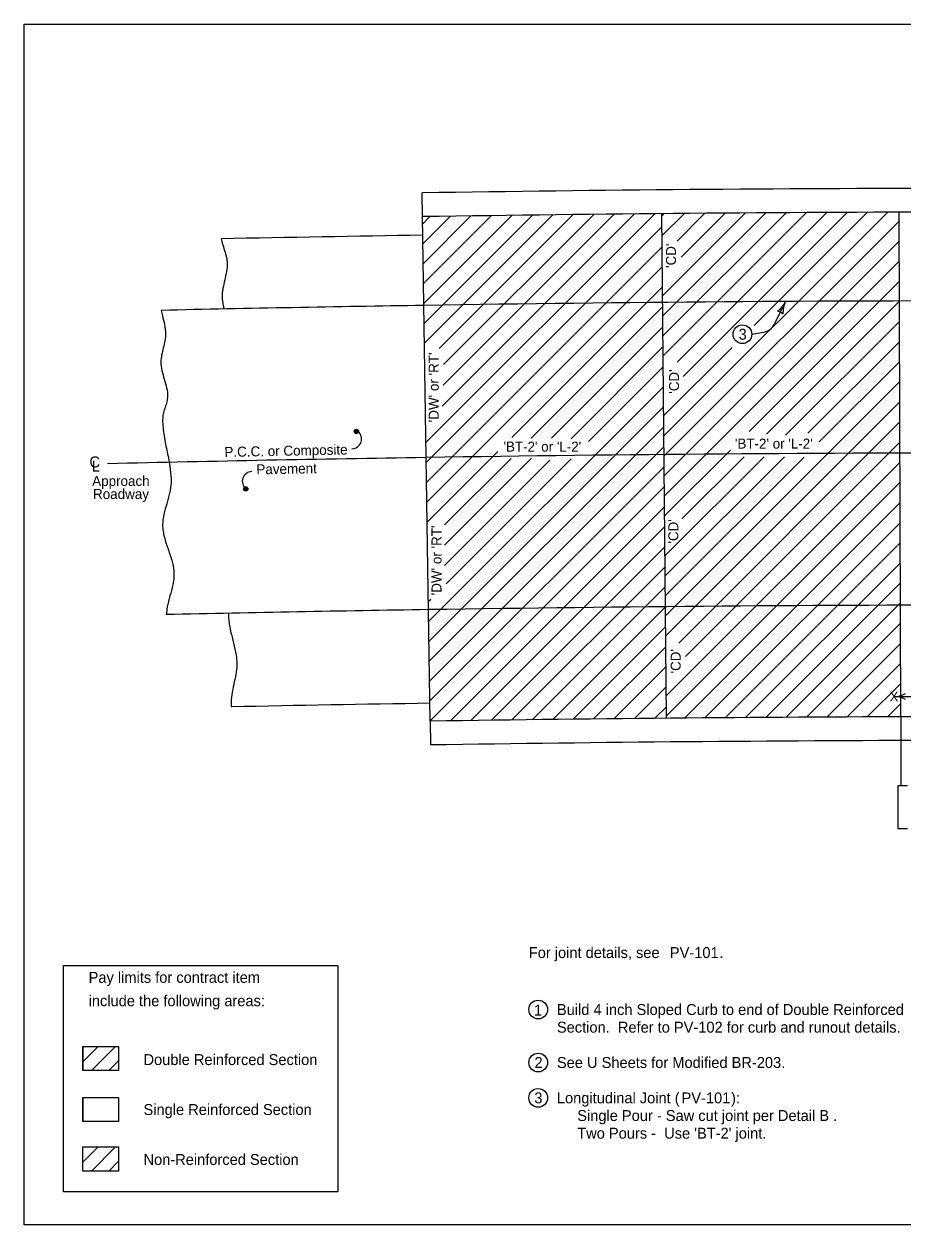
# Model space of a CAD drawing. Extents: x 10130 to 81668, y 5440 to 21644.
# Drawn here: x 20933 to 22410, y 7924 to 9944 of the extents above; entities that cross this region are included whole.
import ezdxf

# ---------------------------------------------------------------- set-up
doc = ezdxf.new("R2010")
doc.units = 0
for name, color, linetype in [('Default', 7, 'Continuous'), ('dsnStdBlockModified', 7, 'Continuous'), ('dsnStdBorder', 7, 'Continuous'), ('dsnstdModifiedBlock', 7, 'Continuous'), ('SheetBorder', 7, 'Continuous')]:
    doc.layers.add(name, color=color, linetype=linetype)

msp = doc.modelspace()

# ---------------------------------------------------------------- linework, layer by layer
at = {"layer": 'Default'}
for p, q in [((21602.2, 9620), (21601.6, 9660)), ((21615.3, 8771.5), (21615.9, 8731.5))]:
    msp.add_line(p, q, dxfattribs=at)
for radius, start in [(65123.7, 89.30428), (64195, 89.350122)]:
    msp.add_arc((22609.7, -55455.9), radius, start, 90.886963, dxfattribs=at)
for points in [[(21264.2, 9582.7), (21265.1, 9578.5), (21268.6, 9566.3), (21272.2, 9554.1), (21273.5, 9548), (21273.9, 9544.9), (21274.1, 9541.8), (21272.9, 9527.7), (21269.9, 9513.6), (21266.9, 9499.5), (21265.8, 9492.4), (21265.6, 9488.9), (21265.6, 9485.4), (21267.4, 9470.4), (21268.7, 9464.7)], [(21163, 9462.4), (21165.2, 9453.1), (21168.8, 9438.2), (21170.5, 9423.2), (21169.4, 9411.3), (21166.6, 9399.5), (21163.9, 9387.7), (21162.5, 9375.9), (21164.3, 9361.2), (21168.3, 9346.6), (21172.2, 9331.9), (21173.8, 9317.3), (21172.5, 9308.4), (21169.8, 9299.5), (21167, 9290.7), (21165.6, 9281.7), (21165.9, 9268.2), (21167.5, 9254.6), (21172.5, 9227.3), (21177.7, 9200), (21179.6, 9179.6), (21179.7, 9172.8), (21177.3, 9155), (21172.5, 9137.2), (21167.7, 9119.4), (21165.5, 9101.6), (21166.3, 9091.2), (21168.4, 9080.8), (21174.9, 9060.3), (21181.5, 9039.8), (21184.6, 9019.2), (21184.1, 9009.9), (21182.5, 9000.7), (21177.9, 8982.1), (21173.3, 8963.5), (21171.6, 8950.6)], [(21276.5, 8952.9), (21276.4, 8947.2), (21276.6, 8942.2), (21277.1, 8937.2), (21278.8, 8927.3), (21283.5, 8907.5), (21288.1, 8887.6), (21289.8, 8877.7), (21290.1, 8872.7), (21290.3, 8867.7), (21289.9, 8859), (21288.6, 8850.4), (21285.1, 8833.2), (21281.8, 8815.9), (21280.9, 8798.6), (21281.1, 8795.5)]]:
    msp.add_spline(points, degree=3, dxfattribs=at)
at = {"layer": 'dsnStdBlockModified'}
for p, q in [((22194.2, 9439.4), (22212.9, 9477.3)), ((22155.9, 9422.2), (22175.4, 9425.5)), ((22394.6, 8812.8), (22425.9, 8812.8)), ((21031.6, 8224.3), (21091.3, 8224.3)), ((21031.6, 8183.8), (21031.6, 8224.3)), ((21091.3, 8224.3), (21091.3, 8183.8)), ((21091.3, 8183.8), (21031.6, 8183.8)), ((21031.6, 8138.2), (21091.3, 8138.2)), ((21031.6, 8097.8), (21031.6, 8138.2)), ((21091.3, 8138.2), (21091.3, 8097.8)), ((21091.3, 8097.8), (21031.6, 8097.8))]:
    msp.add_line(p, q, dxfattribs=at)
for centre, radius, start, end in [((22171.2, 9450.8), 25.7, 279.5323, 333.7542), ((21483.5, 9246.1), 16.5, 271.1774, 49.8682), ((21316, 9174.8), 16.5, 91.1774, 229.8683)]:
    msp.add_arc(centre, radius, start, end, dxfattribs=at)
at = {"layer": 'dsnStdBorder'}
for p, q in [((21602.4, 9607.6), (21615, 9620.2)), ((21602.9, 9574.1), (21649.5, 9620.7)), ((21603.4, 9540.7), (21683.9, 9621.2)), ((21603.9, 9507.3), (21718.4, 9621.7)), ((21604.4, 9473.9), (21752.8, 9622.2)), ((21605, 9440.4), (21787.2, 9622.6)), ((21605.5, 9407), (21821.5, 9623.1)), ((21608.1, 9239.9), (21993.1, 9624.9)), ((21630.5, 9398.1), (21855.9, 9623.5)), ((21635.7, 9301.5), (21958.8, 9624.6)), ((21637, 9336.7), (21924.5, 9624.2)), ((21637.8, 9371.5), (21890.2, 9623.9)), ((22004.7, 9621.1), (22008.6, 9625.1)), ((22005, 9587.5), (22042.9, 9625.4)), ((22005.9, 9486.6), (22145.5, 9626.2)), ((22006.3, 9453), (22179.7, 9626.4)), ((22006.6, 9419.3), (22213.9, 9626.6)), ((22006.9, 9385.7), (22248, 9626.8)), ((22008.1, 9251.2), (22384.4, 9627.4)), ((22030.4, 9375.3), (22282.1, 9627)), ((22030.4, 9578.9), (22077.1, 9625.6)), ((22037.3, 9551.9), (22111.3, 9625.9)), ((22040.4, 9351.4), (22316.2, 9627.2)), ((22160.1, 9437.1), (22350.3, 9627.3)), ((21608.6, 9206.5), (22004.9, 9602.7)), ((22008.4, 9217.6), (22404.1, 9613.2)), ((22008.8, 9183.9), (22404.2, 9579.4)), ((21609.1, 9173), (22005.2, 9569.1)), ((21609.6, 9139.6), (22005.5, 9535.5)), ((22009.1, 9150.3), (22404.3, 9545.5)), ((21752.5, 9248.5), (22005.8, 9501.9)), ((22151.5, 9258.8), (22404.4, 9511.7)), ((22180.7, 9254.1), (22404.5, 9477.9)), ((21785.3, 9247.4), (22006.1, 9468.2)), ((21819, 9247.2), (22006.4, 9434.6)), ((22212.8, 9252.2), (22404.6, 9444)), ((21852.2, 9246.4), (22006.7, 9401)), ((22007.8, 9284.8), (22123.2, 9400.2)), ((22250.2, 9255.7), (22404.7, 9410.2)), ((22269.5, 9241.1), (22404.8, 9376.4)), ((21881.7, 9242), (22007, 9367.3)), ((21612.7, 8939.1), (22007.4, 9333.7)), ((22010.9, 8948.5), (22404.9, 9342.5)), ((21613.2, 8905.7), (22007.7, 9300.1)), ((22011.3, 8914.9), (22405, 9308.7)), ((22033.1, 8902.8), (22405.1, 9274.9)), ((21613.8, 8872.2), (22008, 9266.5)), ((21614.3, 8838.8), (22008.3, 9232.8)), ((22044.4, 8880.2), (22405.2, 9241)), ((21610.1, 9106.2), (21729.1, 9225.2)), ((21639.2, 9067.4), (21785.6, 9213.8)), ((21639.5, 9101.6), (21751.3, 9213.5)), ((21642.3, 9002.6), (21852.5, 9212.8)), ((22009.4, 9116.7), (22120, 9227.3)), ((22010, 9049.4), (22176.9, 9216.3)), ((22010.3, 9015.8), (22210.7, 9216.1)), ((22010.6, 8982.2), (22244, 9215.6)), ((22038.9, 9112.3), (22142.9, 9216.2)), ((21614.8, 8805.4), (22008.6, 9199.2)), ((21639.3, 9033.5), (21816.4, 9210.6)), ((22012.2, 8814), (22405.3, 9207.2)), ((22012.5, 8780.4), (22405.5, 9173.3)), ((21615.3, 8772), (22008.9, 9165.6)), ((21649.3, 8772), (22009.2, 9131.9)), ((22042.7, 8776.7), (22405.6, 9139.5)), ((21683.7, 8772.5), (22009.5, 9098.3)), ((22077, 8777), (22405.7, 9105.7)), ((22111.2, 8777.2), (22405.8, 9071.8)), ((21718.2, 8773), (22009.9, 9064.7)), ((21752.6, 8773.4), (22010.2, 9031.1)), ((22145.4, 8777.5), (22405.9, 9038)), ((21787, 8773.9), (22010.5, 8997.4)), ((22179.5, 8777.7), (22406, 9004.2)), ((21612.2, 8972.5), (21616.5, 8976.8)), ((22213.7, 8777.9), (22406.1, 8970.3)), ((21821.3, 8774.3), (22010.8, 8963.8)), ((21855.7, 8774.7), (22011.1, 8930.2)), ((22247.8, 8778.1), (22406.2, 8936.5)), ((21890, 8775.1), (22011.4, 8896.5)), ((22282, 8778.3), (22406.3, 8902.7)), ((22316.1, 8778.5), (22406.4, 8868.8)), ((21924.3, 8775.5), (22011.7, 8862.9)), ((21958.6, 8775.9), (22012, 8829.3)), ((22350.2, 8778.6), (22406.5, 8835)), ((21992.9, 8776.2), (22012.4, 8795.7)), ((22384.2, 8778.8), (22406.6, 8801.1)), ((22406.7, 8778.8), (22406.7, 8663.1)), ((22401.5, 8663.1), (22418, 8663.1)), ((22401.5, 8663.1), (22401.5, 8590.7)), ((22401.5, 8590.7), (22418, 8590.7)), ((21031.6, 8224.3), (21091.3, 8224.3)), ((21031.6, 8224.3), (21031.6, 8183.8)), ((21031.6, 8198.7), (21057.3, 8224.3)), ((21045.9, 8183.8), (21086.4, 8224.3)), ((21091.3, 8224.3), (21091.3, 8183.8)), ((21091.3, 8183.8), (21031.6, 8183.8)), ((21075, 8183.8), (21091.3, 8200.2)), ((21031.6, 8138.2), (21091.3, 8138.2)), ((21031.6, 8138.2), (21031.6, 8097.8)), ((21091.3, 8138.2), (21091.3, 8097.8)), ((21091.3, 8097.8), (21031.6, 8097.8)), ((21031.6, 8029.6), (21057.3, 8055.3)), ((21045.9, 8014.8), (21086.4, 8055.3)), ((21075, 8014.8), (21091.3, 8031.2))]:
    msp.add_line(p, q, dxfattribs=at)
for points in [[(21491.7, 9255.4), (21490.5, 9255.9), (21488.6, 9256.4), (21488.2, 9258.4), (21488.4, 9260.1), (21489.6, 9261.6), (21491.4, 9261.5), (21493.3, 9261.3), (21494.3, 9259.8), (21494.5, 9258.2), (21493.4, 9256.1), (21492, 9255.9), (21490.1, 9256.3), (21488.5, 9257.5), (21488.5, 9259.3), (21489.7, 9260.8), (21491.4, 9261), (21493.3, 9260.7), (21493.6, 9259.6), (21494, 9258.3), (21493.2, 9256.7), (21491.8, 9256.7), (21490.2, 9257), (21489, 9257.8), (21489.6, 9259.4), (21490.8, 9260.4), (21492.3, 9260.4), (21492.8, 9259.6), (21493.3, 9258.6), (21492.5, 9257.4), (21491.4, 9257.1), (21490.3, 9257.6), (21490.2, 9258.8), (21490.7, 9259.6), (21491.8, 9259.9), (21492.3, 9259.5), (21492.7, 9258.9), (21492.1, 9257.9), (21491.4, 9257.7), (21490.6, 9258.1), (21490.7, 9258.8), (21491.3, 9259.2), (21492, 9259.2), (21492, 9258.6), (21491.4, 9258.3)], [(21305.7, 9158.8), (21304.5, 9159.3), (21302.6, 9159.9), (21302.1, 9161.8), (21302.4, 9163.5), (21303.6, 9165.1), (21305.4, 9165), (21307.3, 9164.7), (21308.2, 9163.2), (21308.4, 9161.6), (21307.3, 9159.5), (21306, 9159.3), (21304, 9159.8), (21302.5, 9160.9), (21302.5, 9162.7), (21303.7, 9164.2), (21305.4, 9164.4), (21307.3, 9164.1), (21307.6, 9163), (21308, 9161.7), (21307.1, 9160.2), (21305.7, 9160.2), (21304.2, 9160.4), (21303, 9161.3), (21303.5, 9162.8), (21304.7, 9163.8), (21306.3, 9163.9), (21306.7, 9163), (21307.3, 9162.1), (21306.5, 9160.8), (21305.3, 9160.5), (21304.3, 9161), (21304.2, 9162.2), (21304.7, 9163), (21305.8, 9163.4), (21306.3, 9162.9), (21306.6, 9162.3), (21306.1, 9161.3), (21305.3, 9161.1), (21304.6, 9161.6), (21304.7, 9162.2), (21305.2, 9162.6), (21306, 9162.6), (21306, 9162.1), (21305.3, 9161.8)]]:
    msp.add_lwpolyline(points, dxfattribs=at)
for points in [[(20998.9, 8360.3), (21460.2, 8360.3), (21460.2, 7980), (20998.9, 7980)], [(21031.6, 8055.3), (21091.3, 8055.3), (21091.3, 8014.8), (21031.6, 8014.8)]]:
    msp.add_lwpolyline(points, close=True, dxfattribs=at)
for centre, radius in [((22140.2, 9422.2), 15.7), ((21491.4, 9258.7), 3.62), ((21305.3, 9162.1), 3.62), ((21796.9, 8286.4), 15.7), ((21796.9, 8197.2), 15.7), ((21796.9, 8137.8), 15.7)]:
    msp.add_circle(centre, radius, dxfattribs=at)
for centre, radius, start, end in [((22609.7, -55455.9), 64934.4, 89.104273, 90.886963), ((22173.1, 9496.9), 44.4, 305.682, 333.7545), ((22252.7, 9457.7), 44.4, 153.7545, 181.8269), ((22196.4, 9443.9), 17.1, 46.0211, 81.4878), ((22609.7, -55455.9), 64678.5, 90.886963, 91.361496), ((22609.7, -55455.9), 64422.6, 89.132259, 90.886963), ((22394.6, 8855.1), 42.3, 270, 298.0725), ((22394.6, 8770.5), 42.3, 61.9275, 90)]:
    msp.add_arc(centre, radius, start, end, dxfattribs=at)
at = {"layer": 'dsnstdModifiedBlock'}
for p, q in [((21615.3, 8771.5), (21602.2, 9620)), ((22012.5, 8776.4), (22004.7, 9625)), ((22406.7, 8778.8), (22404, 9627.5))]:
    msp.add_line(p, q, dxfattribs=at)
for radius, start, end in [(65083.7, 89.30428, 90.886963), (65052.5, 90.886963, 91.185087), (64934.4, 90.886963, 91.276605), (64678.5, 89.11821, 90.886963), (64422.6, 90.886963, 91.279119), (64265.1, 90.886963, 91.184543), (64235, 89.350122, 90.886963)]:
    msp.add_arc((22609.7, -55455.9), radius, start, end, dxfattribs=at)
at = {"layer": 'SheetBorder'}
msp.add_lwpolyline([(20932.5, 9944), (24067.5, 9944), (24067.5, 7924), (20932.5, 7924)], close=True, dxfattribs=at)

# ---------------------------------------------------------------- texts
at = {"layer": 'dsnStdBlockModified'}
for s, height, rotation, p in [("'CD'", 16.8, 90, (22028.5, 9533.7)), ("'DW' or 'RT'", 16.884, 90, (21629.7, 9274.1)), ("'CD'", 16.8, 90, (22033.6, 9322.1)), ('P.C.C. or Composite', 16.884, 1.1774, (21269.6, 9215.7)), ('Pavement', 16.88, 1.1774, (21323.3, 9186.4)), ("'DW' or 'RT'", 16.884, 90, (21634.4, 8983.1)), ("'CD'", 16.8, 90, (22032.4, 9070.1)), ("'CD'", 16.8, 90, (22036.4, 8851.7))]:
    msp.add_text(s, height=height, rotation=rotation, dxfattribs=at).set_placement(p)
for s, height, p in [('3', 18.4, (22133.8, 9413)), ("'BT-2' or 'L-2'", 16.8, (21738.5, 9224.8)), ("'BT-2' or 'L-2'", 16.8, (22127.6, 9229.9)), ('C', 18.5, (21042.5, 9198.2)), ('L', 18.5, (21046.4, 9191)), ('Approach', 16.88, (21047.1, 9167)), ('Roadway', 16.88, (21048.5, 9145.1)), ('X', 16, (22387.9, 8804.8)), ('For joint details, see ', 18.375, (21781.1, 8373)), ('PV-101', 18.37, (22018.3, 8373)), ('PV-101', 18.37, (22018.3, 8373)), ('.', 18.4, (22101.6, 8373)), ('Pay limits for contract item', 18.375, (21041.1, 8331.3)), ('include the following areas:', 18.375, (21041.1, 8292)), ('1', 18.4, (21789.7, 8276.1)), ('Build 4 inch Sloped Curb to end of Double Reinforced', 18.375, (21828.4, 8277.2)), ('Section.  Refer to PV-102 for curb and runout details.', 18.375, (21828.4, 8247.5)), ('Double Reinforced Section', 18.375, (21133.4, 8193)), ('2', 18.4, (21790.6, 8188.1)), ('See U Sheets for Modified BR-203.', 18.375, (21828.4, 8188.1)), ('3', 18.4, (21790.4, 8128.6)), ('Longitudinal Joint (', 18.375, (21828.4, 8128.6)), ('PV-101', 18.37, (22037.9, 8128.6)), ('PV-101', 18.37, (22037.9, 8128.6)), ('):', 18.37, (22121.1, 8128.6)), ('Single Reinforced Section', 18.375, (21133.4, 8109)), ('     Single Pour - Saw cut joint per Detail B .', 18.375, (21828.4, 8098.9)), ("     Two Pours -  Use 'BT-2' joint.", 18.375, (21828.4, 8069.2)), ('Non-Reinforced Section', 18.375, (21133.4, 8025))]:
    msp.add_text(s, height=height, dxfattribs=at).set_placement(p)

doc.saveas('drawing.dxf')
